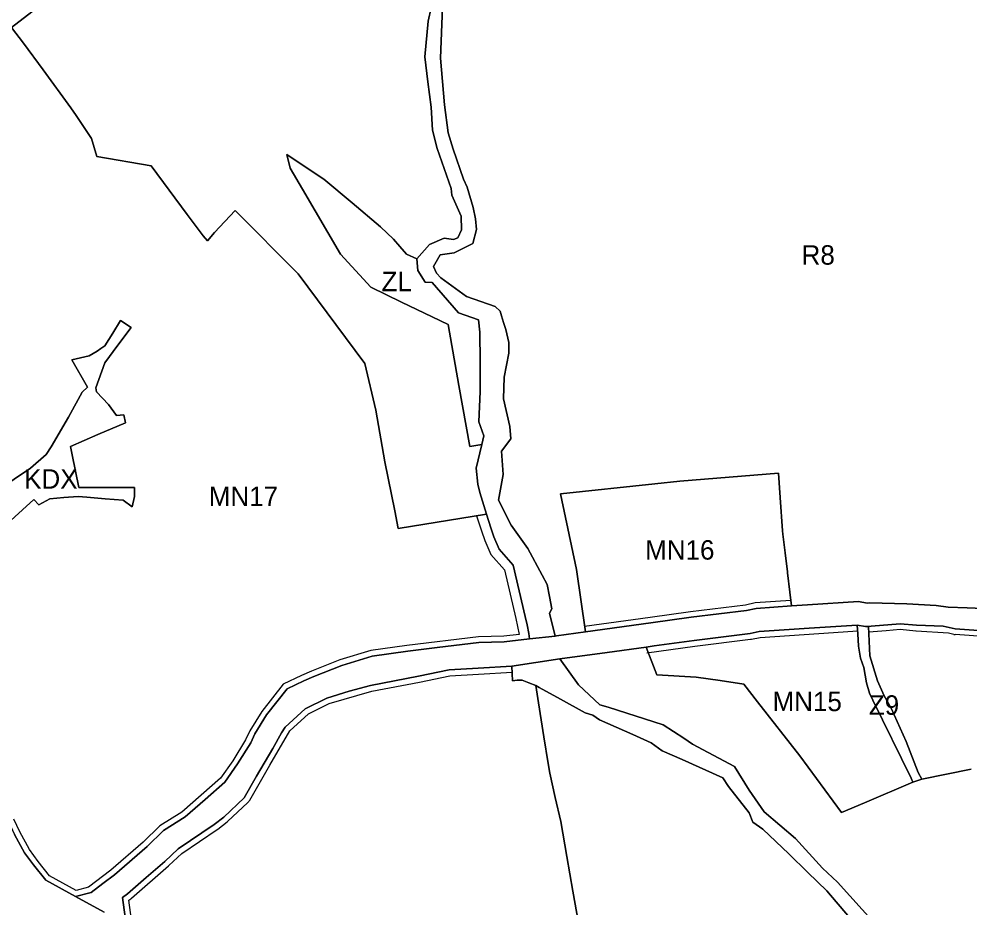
# Model space of a CAD drawing. Extents: x 7440055 to 7442242, y 5549003 to 5552256.
# Drawn here: x 7441014 to 7441503.4, y 5550680.3 to 5551137.8 of the extents above; entities that cross this region are included whole.
import ezdxf

# ---------------------------------------------------------------- set-up
doc = ezdxf.new("R2010")
doc.units = 0
for name, color, linetype in [('linie_rozgraniczajace', 7, 'Continuous'), ('linie_zabudowy_nieprzekraczalne', 7, 'Continuous'), ('oznaczenia_przeznaczen', 7, 'Continuous')]:
    doc.layers.add(name, color=color, linetype=linetype)

msp = doc.modelspace()

# ---------------------------------------------------------------- linework, layer by layer
at = {"layer": 'linie_rozgraniczajace'}
for points in [[(7441244.59, 5551051.25), (7441242.8, 5551055.32), (7441237.46, 5551070.83), (7441234.84, 5551079.14), (7441233.01, 5551093.6), (7441230.98, 5551117.63), (7441231.98, 5551143.95), (7441230.21, 5551153.9), (7441224.08, 5551162.79), (7441216.03, 5551165.84), (7441209.02, 5551168.74)], [(7441226.1, 5551143.57), (7441224.56, 5551136.62), (7441222.81, 5551118.36), (7441224.5, 5551105.41), (7441226.19, 5551092.46), (7441226.81, 5551080.52), (7441229.27, 5551071.19), (7441232.88, 5551060.86), (7441236.49, 5551050.52), (7441236.78, 5551047.06), (7441241.56, 5551036.3), (7441241.71, 5551029.27), (7441239.94, 5551025.21), (7441237.57, 5551024.28), (7441232.82, 5551025.07), (7441225.31, 5551021.8), (7441218.7, 5551014.41), (7441213.48, 5551016.81), (7441210.08, 5551020.62), (7441206.69, 5551024.42), (7441200, 5551030.87), (7441185.42, 5551043.09), (7441170.84, 5551055.31), (7441161.32, 5551061.64), (7441151.8, 5551067.96), (7441153.66, 5551061.05), (7441159.92, 5551050.28), (7441179.47, 5551016.67), (7441195.14, 5550999.76), (7441210.92, 5550992.13), (7441226.69, 5550984.51), (7441234.96, 5550980.5), (7441240.46, 5550949.18), (7441245.96, 5550917.85), (7441252.15, 5550918.82), (7441249.28, 5550906.62), (7441250.2, 5550898.32), (7441251.21, 5550894.15), (7441254.54, 5550882.93), (7441209.24, 5550875.6), (7441207.41, 5550884.58), (7441202.26, 5550909.81), (7441197.72, 5550936.52), (7441192.03, 5550960.45), (7441157.75, 5551006.67), (7441125.32, 5551039.19), (7441114.63, 5551027.9), (7441111.09, 5551023.65), (7441108.77, 5551026.18), (7441104.68, 5551031.71), (7441100.59, 5551037.24), (7441091.29, 5551049.73), (7441081.99, 5551062.22), (7441054.03, 5551067.05), (7441051.41, 5551076.23), (7441043.39, 5551088.16), (7441040.71, 5551092.13), (7441026.4, 5551111.65), (7441016.3, 5551125.31), (7441010.11, 5551133.47), (7441029.47, 5551148.49)], [(7441029.47, 5551148.49), (7441010.11, 5551133.47), (7441016.3, 5551125.31), (7441026.4, 5551111.65), (7441040.71, 5551092.13), (7441043.39, 5551088.16), (7441051.41, 5551076.23), (7441054.03, 5551067.05), (7441081.99, 5551062.22), (7441091.29, 5551049.73), (7441100.59, 5551037.24), (7441104.68, 5551031.71), (7441108.77, 5551026.18), (7441111.09, 5551023.65), (7441114.63, 5551027.9), (7441125.32, 5551039.19), (7441157.75, 5551006.67), (7441192.03, 5550960.45), (7441197.72, 5550936.52), (7441202.26, 5550909.81), (7441207.41, 5550884.58), (7441209.24, 5550875.6), (7441254.54, 5550882.93), (7441256.85, 5550875.88), (7441258.38, 5550871.23), (7441261.17, 5550864.87), (7441264.78, 5550860.79), (7441268.4, 5550856.71), (7441271.48, 5550843.5), (7441274.56, 5550830.28), (7441275.47, 5550825.91), (7441276.38, 5550821.53), (7441276.67, 5550818.7), (7441263.75, 5550817.21), (7441250.71, 5550816.87), (7441229.24, 5550814.28), (7441214.05, 5550812.46), (7441195.76, 5550809.79), (7441180.17, 5550805.14), (7441165.78, 5550799.39), (7441160.63, 5550797.15), (7441151.97, 5550793.01), (7441146.69, 5550786.38), (7441141.4, 5550779.75), (7441135.41, 5550769.97), (7441133.31, 5550765.33), (7441126.51, 5550754.41), (7441119.97, 5550745.06), (7441109.79, 5550736.09), (7441099.61, 5550727.12), (7441088.4, 5550720.13), (7441080.01, 5550711.89), (7441063.12, 5550697.34), (7441057.15, 5550692.82), (7441051.19, 5550688.29), (7441043.14, 5550686.11), (7441027.75, 5550694.5), (7441021.5, 5550702.43), (7441016.81, 5550708.73), (7441011.75, 5550718.07)], [(7441251.3, 5550961.32), (7441251.2, 5550976.57), (7441250.52, 5550982.96), (7441240.18, 5550986.5), (7441226.58, 5551002.2), (7441223.07, 5551002.31), (7441219.34, 5551008.37), (7441218.7, 5551014.41), (7441225.31, 5551021.8), (7441232.82, 5551025.07), (7441237.57, 5551024.28), (7441239.94, 5551025.21), (7441241.71, 5551029.27), (7441241.56, 5551036.3), (7441236.78, 5551047.06), (7441236.49, 5551050.52), (7441232.88, 5551060.86), (7441229.27, 5551071.19), (7441226.81, 5551080.52), (7441226.19, 5551092.46), (7441224.5, 5551105.41), (7441222.81, 5551118.36), (7441224.56, 5551136.62), (7441226.1, 5551143.57)], [(7441231.98, 5551143.95), (7441230.98, 5551117.63), (7441233.01, 5551093.6), (7441234.84, 5551079.14), (7441237.46, 5551070.83), (7441242.8, 5551055.32), (7441244.59, 5551051.25), (7441247.76, 5551040.83), (7441248.95, 5551034.88), (7441249.55, 5551029.47), (7441247.64, 5551022.17), (7441237.9, 5551017.39), (7441230.86, 5551016.38), (7441227.33, 5551010.39), (7441228.97, 5551006.91), (7441231.09, 5551004.62), (7441244.41, 5550994.94), (7441259.07, 5550989.81), (7441261.71, 5550987.44), (7441262.28, 5550985.06), (7441263.41, 5550981.55), (7441264.54, 5550978.05), (7441266.09, 5550971.34), (7441266.1, 5550965.87), (7441263.63, 5550953.51), (7441263.4, 5550942.32), (7441266.68, 5550928.1), (7441267.15, 5550921.73), (7441262.32, 5550915.37), (7441263.18, 5550903.4), (7441260.83, 5550890.07), (7441267.29, 5550877.22), (7441275.97, 5550865.27), (7441283.29, 5550851.59), (7441285.87, 5550846.77), (7441287.09, 5550840.54), (7441288.31, 5550834.31), (7441286.99, 5550831.97), (7441289.89, 5550820.22), (7441276.67, 5550818.7), (7441276.38, 5550821.53), (7441275.47, 5550825.91), (7441274.56, 5550830.28), (7441271.48, 5550843.5), (7441268.4, 5550856.71), (7441264.78, 5550860.79), (7441261.17, 5550864.87), (7441258.38, 5550871.23), (7441256.85, 5550875.88), (7441254.54, 5550882.93), (7441251.21, 5550894.15), (7441250.2, 5550898.32), (7441249.28, 5550906.62), (7441252.15, 5550918.82), (7441253.18, 5550923.2), (7441250.61, 5550930.39), (7441251.41, 5550946.07), (7441251.3, 5550961.32)], [(7441530.39, 5550833.54), (7441501.97, 5550834.71), (7441492.13, 5550835.09), (7441486.02, 5550835.93), (7441470.96, 5550836.88), (7441451.83, 5550837.23), (7441450.46, 5550837.18), (7441446, 5550837.92), (7441419.85, 5550836.28), (7441411.57, 5550835.71), (7441410.72, 5550842.79), (7441409.52, 5550852.76), (7441409.45, 5550853.33), (7441408.28, 5550863.02), (7441407.11, 5550872.71), (7441407, 5550874.32), (7441405.79, 5550891.53), (7441404.92, 5550904.05), (7441354.13, 5550899.9), (7441341.21, 5550898.54), (7441292.66, 5550893.42), (7441300.99, 5550854.46), (7441305.56, 5550822.37), (7441290.64, 5550820.3), (7441289.89, 5550820.22), (7441286.99, 5550831.97), (7441288.31, 5550834.31), (7441287.09, 5550840.54), (7441285.87, 5550846.77), (7441283.29, 5550851.59), (7441275.97, 5550865.27), (7441267.29, 5550877.22), (7441260.83, 5550890.07), (7441263.18, 5550903.4), (7441262.32, 5550915.37), (7441267.15, 5550921.73), (7441266.68, 5550928.1), (7441263.4, 5550942.32), (7441263.63, 5550953.51), (7441266.1, 5550965.87), (7441266.09, 5550971.34), (7441264.54, 5550978.05), (7441263.41, 5550981.55), (7441262.28, 5550985.06), (7441261.71, 5550987.44), (7441259.07, 5550989.81), (7441244.41, 5550994.94), (7441231.09, 5551004.62), (7441228.97, 5551006.91), (7441227.33, 5551010.39), (7441230.86, 5551016.38), (7441237.9, 5551017.39), (7441247.64, 5551022.17), (7441249.55, 5551029.47), (7441248.95, 5551034.88), (7441247.76, 5551040.83), (7441244.59, 5551051.25)], [(7441058.35, 5550890.92), (7441067.7, 5550890.12), (7441072.32, 5550886.68), (7441073.53, 5550892.1), (7441073.38, 5550896.59), (7441044.81, 5550896.63), (7441043.11, 5550905.09), (7441041.41, 5550913.55), (7441040.47, 5550917.79), (7441054.64, 5550923.89), (7441068.81, 5550929.99), (7441067.92, 5550934.07), (7441064.25, 5550933.8), (7441060.01, 5550939.43), (7441056.97, 5550942.58), (7441053.86, 5550945.85), (7441053.57, 5550947.98), (7441058.13, 5550960.9), (7441064.97, 5550969.92), (7441071.82, 5550978.94), (7441066.33, 5550982.58), (7441062.24, 5550976.06), (7441058.15, 5550969.53), (7441056.22, 5550968.21), (7441054.28, 5550966.88), (7441052.22, 5550965.67), (7441050.15, 5550964.46), (7441041.2, 5550962.41), (7441049.21, 5550948.35), (7441046.59, 5550945.76), (7441039.42, 5550932.9), (7441030.6, 5550917.64), (7441028.02, 5550913.61), (7441019.97, 5550906.59), (7441003.04, 5550895.28)], [(7441003.04, 5550895.28), (7441019.97, 5550906.59), (7441028.02, 5550913.61), (7441030.6, 5550917.64), (7441039.42, 5550932.9), (7441046.59, 5550945.76), (7441049.21, 5550948.35), (7441041.2, 5550962.41), (7441050.15, 5550964.46), (7441052.22, 5550965.67), (7441054.28, 5550966.88), (7441056.22, 5550968.21), (7441058.15, 5550969.53), (7441062.24, 5550976.06), (7441066.33, 5550982.58), (7441071.82, 5550978.94), (7441064.97, 5550969.92), (7441058.13, 5550960.9), (7441053.57, 5550947.98), (7441053.86, 5550945.85), (7441056.97, 5550942.58), (7441060.01, 5550939.43), (7441064.25, 5550933.8), (7441067.92, 5550934.07), (7441068.81, 5550929.99), (7441054.64, 5550923.89), (7441040.47, 5550917.79), (7441041.41, 5550913.55), (7441043.11, 5550905.09), (7441044.81, 5550896.63), (7441073.38, 5550896.59), (7441073.53, 5550892.1), (7441072.32, 5550886.68), (7441067.7, 5550890.12), (7441058.35, 5550890.92), (7441049, 5550891.72), (7441044.5, 5550892.11), (7441037.16, 5550891.45), (7441029.83, 5550890.79), (7441024.16, 5550887.83), (7441021.65, 5550890.55), (7441006.03, 5550876.25)], [(7441006.03, 5550876.25), (7441021.65, 5550890.55), (7441024.16, 5550887.83), (7441029.83, 5550890.79), (7441037.16, 5550891.45), (7441044.5, 5550892.11), (7441049, 5550891.72), (7441058.35, 5550890.92)], [(7441043.14, 5550686.11), (7441051.19, 5550688.29), (7441057.15, 5550692.82), (7441063.12, 5550697.34), (7441080.01, 5550711.89), (7441088.4, 5550720.13), (7441099.61, 5550727.12), (7441109.79, 5550736.09), (7441119.97, 5550745.06), (7441126.51, 5550754.41), (7441133.31, 5550765.33), (7441135.41, 5550769.97), (7441141.4, 5550779.75), (7441146.69, 5550786.38), (7441151.97, 5550793.01), (7441160.63, 5550797.15), (7441165.78, 5550799.39), (7441180.17, 5550805.14), (7441195.76, 5550809.79), (7441214.05, 5550812.46), (7441229.24, 5550814.28), (7441250.71, 5550816.87), (7441263.75, 5550817.21), (7441276.67, 5550818.7), (7441289.89, 5550820.22), (7441290.64, 5550820.3), (7441305.56, 5550822.37), (7441339.26, 5550827.03), (7441359.98, 5550829.89), (7441388.35, 5550833.38), (7441393.35, 5550834.43), (7441411.57, 5550835.71), (7441419.85, 5550836.28), (7441446, 5550837.92), (7441450.46, 5550837.18), (7441451.83, 5550837.23), (7441470.96, 5550836.88), (7441486.02, 5550835.93), (7441492.13, 5550835.09), (7441501.97, 5550834.71), (7441530.39, 5550833.54)], [(7441529.41, 5550821.58), (7441495.87, 5550823.99), (7441489.56, 5550825.24), (7441475.96, 5550825.8), (7441467.48, 5550826.59), (7441452.57, 5550825.25), (7441451.13, 5550825.2), (7441449.68, 5550825.15), (7441445.39, 5550825.86), (7441420.64, 5550824.31), (7441395.02, 5550822.52), (7441390.32, 5550821.53), (7441361.54, 5550817.99), (7441340.91, 5550815.14), (7441336.75, 5550814.57), (7441316.64, 5550811.79), (7441292.37, 5550808.43), (7441267.72, 5550804.64), (7441250.3, 5550803.61), (7441235.4, 5550802.78), (7441219.58, 5550799.49), (7441207.29, 5550797.16), (7441194.99, 5550794.83), (7441183.98, 5550791.9), (7441172.49, 5550788.33), (7441161.3, 5550782.72), (7441150.99, 5550773.38), (7441149.16, 5550770.41), (7441144.64, 5550762.43), (7441136.22, 5550748.07), (7441129.94, 5550736.93), (7441119.36, 5550726.99), (7441114.46, 5550723.18), (7441095.91, 5550710.72), (7441089.05, 5550704.26), (7441079.43, 5550695.88), (7441069.81, 5550687.51), (7441067.3, 5550685.62), (7441069.74, 5550668.05)], [(7441504.13, 5550751.79), (7441478.71, 5550746.62), (7441476.86, 5550750), (7441470.63, 5550766.01), (7441462.84, 5550783.17), (7441459.22, 5550789.4), (7441455.89, 5550797.22), (7441451.86, 5550810.1), (7441451.13, 5550825.2), (7441452.57, 5550825.25), (7441467.48, 5550826.59), (7441475.96, 5550825.8), (7441489.56, 5550825.24), (7441495.87, 5550823.99), (7441529.41, 5550821.58)], [(7441292.37, 5550808.43), (7441316.64, 5550811.79), (7441336.75, 5550814.57), (7441342.26, 5550800.28), (7441362.59, 5550799.04), (7441374.83, 5550797.26), (7441387.07, 5550795.49), (7441394.16, 5550786.42), (7441415.94, 5550758.56), (7441437.38, 5550729.38), (7441449.24, 5550734.44), (7441474.09, 5550745.1), (7441478.71, 5550746.62), (7441504.13, 5550751.79)], [(7440985.92, 5550808.58), (7440988.51, 5550797.2), (7440993.4, 5550776.83), (7440995.7, 5550767.84), (7440998.67, 5550759.48), (7441002.01, 5550744.64), (7441008.62, 5550724.81), (7441011.75, 5550718.07), (7441016.81, 5550708.73), (7441021.5, 5550702.43), (7441027.75, 5550694.5), (7441043.14, 5550686.11), (7441057.84, 5550678.1)], [(7441069.74, 5550668.05), (7441067.3, 5550685.62), (7441069.81, 5550687.51), (7441079.43, 5550695.88), (7441089.05, 5550704.26), (7441095.91, 5550710.72), (7441114.46, 5550723.18), (7441119.36, 5550726.99), (7441129.94, 5550736.93), (7441136.22, 5550748.07), (7441144.64, 5550762.43), (7441149.16, 5550770.41), (7441150.99, 5550773.38), (7441161.3, 5550782.72), (7441172.49, 5550788.33), (7441183.98, 5550791.9), (7441194.99, 5550794.83), (7441207.29, 5550797.16), (7441219.58, 5550799.49), (7441235.4, 5550802.78), (7441250.3, 5550803.61), (7441267.72, 5550804.64), (7441267.84, 5550800.99), (7441268.06, 5550797.25), (7441270.44, 5550797.45), (7441272.93, 5550797.56), (7441276.45, 5550796.15), (7441279.98, 5550794.74), (7441281.38, 5550785.92), (7441282.79, 5550777.11), (7441284.19, 5550768.3), (7441286.38, 5550754.55), (7441287.16, 5550749.61), (7441290.04, 5550737.19), (7441292.93, 5550724.77), (7441295.99, 5550706.84), (7441299.05, 5550688.91), (7441302.05, 5550672.64)], [(7441267.84, 5550800.99), (7441267.72, 5550804.64), (7441292.37, 5550808.43), (7441297.15, 5550801.74), (7441301.92, 5550795.05), (7441307.43, 5550789.96), (7441312.93, 5550784.87), (7441317.21, 5550783.68), (7441345.57, 5550774.59), (7441356.14, 5550767.67), (7441360.66, 5550764.58), (7441382.21, 5550753.12), (7441389.8, 5550740.91), (7441397.57, 5550729.83), (7441413.61, 5550716.02), (7441427.6, 5550700.81), (7441435.31, 5550693.52), (7441454.24, 5550672.51)], [(7441454.24, 5550672.51), (7441435.31, 5550693.52), (7441427.6, 5550700.81), (7441413.61, 5550716.02), (7441397.57, 5550729.83), (7441389.8, 5550740.91), (7441382.21, 5550753.12), (7441360.66, 5550764.58), (7441356.14, 5550767.67), (7441345.57, 5550774.59), (7441317.21, 5550783.68), (7441312.93, 5550784.87), (7441307.43, 5550789.96), (7441301.92, 5550795.05), (7441297.15, 5550801.74), (7441292.37, 5550808.43)], [(7441447.56, 5550668.14), (7441434.5, 5550683.51), (7441429.82, 5550689.02), (7441420, 5550698.57), (7441410.19, 5550708.11), (7441396.82, 5550720.84), (7441391.76, 5550724.39), (7441389.82, 5550729.28), (7441379.2, 5550742.78), (7441376.23, 5550747.27), (7441355.36, 5550756.68), (7441345.11, 5550761.1), (7441339.34, 5550765.34), (7441329.9, 5550769.54), (7441312.8, 5550777.12), (7441309.31, 5550779.47), (7441305.45, 5550780.74), (7441292.71, 5550787.74), (7441281.7, 5550793.79), (7441279.98, 5550794.74), (7441276.45, 5550796.15), (7441272.93, 5550797.56), (7441270.44, 5550797.45), (7441268.06, 5550797.25), (7441267.84, 5550800.99)], [(7441279.98, 5550794.74), (7441281.7, 5550793.79), (7441292.71, 5550787.74), (7441305.45, 5550780.74), (7441309.31, 5550779.47), (7441312.8, 5550777.12), (7441329.9, 5550769.54), (7441339.34, 5550765.34), (7441345.11, 5550761.1), (7441355.36, 5550756.68), (7441376.23, 5550747.27), (7441379.2, 5550742.78), (7441389.82, 5550729.28), (7441391.76, 5550724.39), (7441396.82, 5550720.84), (7441410.19, 5550708.11), (7441420, 5550698.57), (7441429.82, 5550689.02), (7441434.5, 5550683.51), (7441447.56, 5550668.14)], [(7441302.05, 5550672.64), (7441299.05, 5550688.91), (7441295.99, 5550706.84), (7441292.93, 5550724.77), (7441290.04, 5550737.19), (7441287.16, 5550749.61), (7441286.38, 5550754.55), (7441284.19, 5550768.3), (7441282.79, 5550777.11), (7441281.38, 5550785.92), (7441279.98, 5550794.74)], [(7441057.84, 5550678.1), (7441043.14, 5550686.11)]]:
    msp.add_lwpolyline(points, dxfattribs=at)
for points in [[(7441151.8, 5551067.96), (7441161.32, 5551061.64), (7441170.84, 5551055.31), (7441185.42, 5551043.09), (7441200, 5551030.87), (7441206.69, 5551024.42), (7441210.08, 5551020.62), (7441213.48, 5551016.81), (7441218.7, 5551014.41), (7441219.34, 5551008.37), (7441223.07, 5551002.31), (7441226.58, 5551002.2), (7441240.18, 5550986.5), (7441250.52, 5550982.96), (7441251.2, 5550976.57), (7441251.3, 5550961.32), (7441251.41, 5550946.07), (7441250.61, 5550930.39), (7441253.18, 5550923.2), (7441252.15, 5550918.82), (7441245.96, 5550917.85), (7441240.46, 5550949.18), (7441234.96, 5550980.5), (7441226.69, 5550984.51), (7441210.92, 5550992.13), (7441195.14, 5550999.76), (7441179.47, 5551016.67), (7441159.92, 5551050.28), (7441153.66, 5551061.05)], [(7441292.66, 5550893.42), (7441341.21, 5550898.54), (7441354.13, 5550899.9), (7441404.92, 5550904.05), (7441405.79, 5550891.53), (7441407, 5550874.32), (7441407.11, 5550872.71), (7441408.28, 5550863.02), (7441409.45, 5550853.33), (7441409.52, 5550852.76), (7441410.72, 5550842.79), (7441411.57, 5550835.71), (7441393.35, 5550834.43), (7441388.35, 5550833.38), (7441359.98, 5550829.89), (7441339.26, 5550827.03), (7441305.56, 5550822.37), (7441300.99, 5550854.46)], [(7441336.75, 5550814.57), (7441340.91, 5550815.14), (7441361.54, 5550817.99), (7441390.32, 5550821.53), (7441395.02, 5550822.52), (7441420.64, 5550824.31), (7441445.39, 5550825.86), (7441445.67, 5550821.36), (7441446.07, 5550815.01), (7441447.18, 5550808.75), (7441448.81, 5550804.03), (7441450.2, 5550796.2), (7441451.79, 5550790.78), (7441453.37, 5550787.16), (7441473.11, 5550747.12), (7441474.09, 5550745.1), (7441449.24, 5550734.44), (7441437.38, 5550729.38), (7441415.94, 5550758.56), (7441394.16, 5550786.42), (7441387.07, 5550795.49), (7441374.83, 5550797.26), (7441362.59, 5550799.04), (7441342.26, 5550800.28)], [(7441445.39, 5550825.86), (7441449.68, 5550825.15), (7441451.13, 5550825.2), (7441451.86, 5550810.1), (7441455.89, 5550797.22), (7441459.22, 5550789.4), (7441462.84, 5550783.17), (7441470.63, 5550766.01), (7441476.86, 5550750), (7441478.71, 5550746.62), (7441474.09, 5550745.1), (7441473.11, 5550747.12), (7441453.37, 5550787.16), (7441451.79, 5550790.78), (7441450.2, 5550796.2), (7441448.81, 5550804.03), (7441447.18, 5550808.75), (7441446.07, 5550815.01), (7441445.67, 5550821.36)]]:
    msp.add_lwpolyline(points, close=True, dxfattribs=at)
at = {"layer": 'linie_zabudowy_nieprzekraczalne'}
for p, q in [((7441460.31, 5550822.93), (7441460.25, 5550822.93)), ((7441090.97, 5550701.95), (7441091.15, 5550702.11))]:
    msp.add_line(p, q, dxfattribs=at)
for points in [[(7441249.54, 5550882.12), (7441252.1, 5550874.32), (7441253.71, 5550869.44), (7441256.91, 5550862.14), (7441263.82, 5550854.34), (7441269.68, 5550829.21), (7441271.36, 5550821.1), (7441263.54, 5550820.21), (7441250.49, 5550819.86), (7441213.66, 5550815.43), (7441195.11, 5550812.73), (7441179.19, 5550807.97), (7441164.62, 5550802.16), (7441159.39, 5550799.88), (7441150.06, 5550795.42), (7441138.94, 5550781.47), (7441132.75, 5550771.37), (7441130.66, 5550766.74), (7441124.01, 5550756.07), (7441117.71, 5550747.08), (7441097.81, 5550729.54), (7441086.53, 5550722.5), (7441077.98, 5550714.1), (7441061.23, 5550699.68), (7441049.84, 5550691.03), (7441043.52, 5550689.32), (7441029.72, 5550696.83), (7441023.88, 5550704.25), (7441019.35, 5550710.35), (7441014.43, 5550719.42), (7441011.42, 5550725.92)], [(7441305.06, 5550825.33), (7441338.85, 5550830), (7441359.6, 5550832.86), (7441387.86, 5550836.34), (7441392.94, 5550837.41), (7441411.18, 5550838.69)], [(7441391.07, 5550818.62), (7441395.43, 5550819.54), (7441433.21, 5550822.09), (7441445.58, 5550822.86)], [(7441460.25, 5550822.93), (7441451.37, 5550822.21)], [(7441475.65, 5550822.81), (7441467.47, 5550823.58), (7441460.31, 5550822.93)], [(7441495.11, 5550821.08), (7441492.32, 5550821.63), (7441475.79, 5550822.8)], [(7441593.58, 5550730.95), (7441580.45, 5550765.62), (7441572.17, 5550786.11), (7441569.05, 5550793.41), (7441565.57, 5550803.84), (7441559.74, 5550809.34), (7441555, 5550812.84), (7441550.89, 5550815.76), (7441544.76, 5550817.18), (7441529.17, 5550818.59), (7441495.84, 5550820.99)], [(7441337.16, 5550811.6), (7441361.92, 5550815.01), (7441390.56, 5550818.54)], [(7441220.22, 5550796.56), (7441235.79, 5550799.8), (7441250.46, 5550800.61)], [(7441250.48, 5550800.62), (7441267.9, 5550801.64)], [(7441132.77, 5550735.83), (7441143.03, 5550753.75), (7441153.35, 5550771.47), (7441163.01, 5550780.22), (7441173.59, 5550785.53), (7441195.69, 5550791.91), (7441220.11, 5550796.54)], [(7441121.51, 5550724.9), (7441131.67, 5550734.44)], [(7441116.38, 5550720.88), (7441121.09, 5550724.54)], [(7441091.15, 5550702.11), (7441097.79, 5550708.37), (7441116.04, 5550720.63)], [(7441071.86, 5550685.32), (7441090.97, 5550701.95)], [(7441115.62, 5550648.54), (7441086.56, 5550656.22), (7441076.89, 5550660.96), (7441072.64, 5550668.99), (7441070.51, 5550684.29), (7441071.53, 5550685.05)]]:
    msp.add_lwpolyline(points, dxfattribs=at)
for centre, radius, start, end in [((7441475.69, 5550822.32), 0.496, 77.7843, 94.0445), ((7441496.01, 5550825.36), 4.37, 258.1447, 267.7985), ((7441390.33, 5550821.66), 3.13, 274.1869, 283.6429), ((7441250.46, 5550800.62), 0.0158, 251.5651, 341.5651), ((7441219.86, 5550798.25), 1.73, 278.4572, 282.1525), ((7441127.66, 5550738.74), 5.88, 312.9796, 330.3065), ((7441117.48, 5550729.18), 5.88, 307.9035, 313.2991), ((7441114.89, 5550722.55), 2.24, 300.923, 311.7306), ((7441069.65, 5550687.68), 3.23, 305.5088, 313.07)]:
    msp.add_arc(centre, radius, start, end, dxfattribs=at)

# ---------------------------------------------------------------- texts
at = {"layer": 'oznaczenia_przeznaczen'}
for s, p in [('R8', (7441416.78, 5551011.36)), ('ZL', (7441200.59, 5550997.71)), ('KDX', (7441016.67, 5550896.07)), ('MN17', (7441111.7, 5550887.15)), ('MN16', (7441336.26, 5550859.55)), ('MN15', (7441401.84, 5550781.57)), ('Z9', (7441451.38, 5550779.71))]:
    msp.add_text(s, height=10, dxfattribs=at).set_placement(p)

doc.saveas('drawing.dxf')
